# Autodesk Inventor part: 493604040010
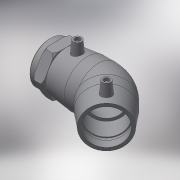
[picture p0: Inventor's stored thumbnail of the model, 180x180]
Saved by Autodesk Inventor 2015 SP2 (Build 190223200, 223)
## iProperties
Created: 2017-06
Part Number: 493604040010
Material: Generic
Description: PLASSON 45° ELBOW TRANSITION FEMALE 40-1"
Document SubType Name: Modeling
Designer: KIM
Mass: 186.717 g
Surface Area: 453.285 cm^2
Volume: 186.717 cm^3
Density: 1 g/cm^3
Appearance: Default
Author: KIM
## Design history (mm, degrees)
derived "493604.ipt"
feature "Solid1::493604.ipt"
tag "TaggingFeature1"
body "Solid1"
other parameters: "d2" = 56, "d4" = 27, "d5" = 50.4, "d8" = 168 deg, "d10" = 17.6, "d11" = 5.86667, "d29" = 47, "d30" = 15, "d31" = 37.8, "d34" = 5 deg, "d41" = 4, "d42" = 14, "d43" = 0, "d50" = 34, "d51" = 17.6, "d52" = 44, "d54" = 135 deg, "d86" = 25.2, "d87" = 135 deg, "d88" = 108, "d90" = 44, "d91" = 0, "d92" = 44, "d93" = 0, "d101" = 3, "d102" = 0, "d107" = 0.1, "d108" = 29, "d110" = 25, "d112" = 50.4, "d113" = 30.291, "d114" = 22.5, "d128" = 15, "d129" = 0, "d132" = 2, "d133" = 45 deg, "d134" = 45 deg, "d136" = 1.2, "L_" = 133, "L_1" = 44, "D_" = 29, "A_" = 47, "d_2" = 12, "L_2" = 25, "Rp_" = 30.291, "D_1" = 56
